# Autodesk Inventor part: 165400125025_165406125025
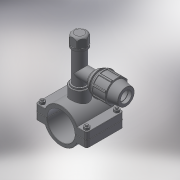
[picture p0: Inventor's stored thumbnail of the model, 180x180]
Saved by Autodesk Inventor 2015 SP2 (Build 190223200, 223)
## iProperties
Created: 2017-05
Part Number: 165400125025_165406125025
Material: Generic
Description: PLASSON TAPPER FOR PE+PVC PIPE 125-25
Document SubType Name: Modeling
Designer: KIM
Density: 1 g/cm^3
Appearance: Default
Author: KIM
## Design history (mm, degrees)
derived "16540.ipt"
feature "Solid1::16540.ipt"
feature "Solid2::16540.ipt"
tag "TaggingFeature1"
body "Solid1"
other parameters: "d0" = 137.5, "d1" = 184, "d2" = 62.5, "d3" = 125, "d4" = 124, "d5" = 0, "d6" = 9.2, "d7" = 184, "d8" = 0.1, "d10" = 0, "d11" = 1.25, "d14" = 39.3783, "d20" = 1.25, "d23" = 1.25, "d36" = 13, "d37" = 10.4, "d38" = 70.5, "d39" = 0, "d40" = 3, "d41" = 5, "d42" = 0, "d43" = 8, "d44" = 3, "d45" = 0, "d46" = 1.25, "d51" = 94, "d52" = 30.291, "d53" = 21, "d54" = 0, "d55" = 25, "d57" = 0, "d58" = 135, "d60" = 0, "d62" = 13, "d63" = 10.4, "d66" = 103.2, "d67" = 25, "d68" = 8.75, "d69" = 21, "d70" = 54, "d71" = 40.5, "d72" = 1.5, "d73" = 43.2, "d74" = 120 deg, "d75" = 37.5, "d76" = 10 deg, "d77" = 48.6, "d78" = 31.5, "d79" = 61, "d81" = 105, "d82" = 6.1, "d87" = 15, "d90" = 50.22, "d91" = 35 deg, "d92" = 17.5 deg, "d94" = 0, "d96" = 360 deg, "d98" = 0.5, "d99" = 67.1, "d100" = 27.2619, "d101" = 135 deg, "d102" = 1.08, "d105" = 2.7, "d106" = 0, "d107" = 0.1, "d108" = 27.2619, "d109" = 33.3201, "d111" = 26.2, "d112" = 6.55, "d113" = 3.5, "d116" = 0, "d118" = 21, "d119" = 0, "d121" = 131, "d122" = 58, "d_" = 125, "B_" = 25, "G_" = 30.291, "A_" = 94, "L_" = 184, "L_1" = 124, "l_2" = 21, "d_1" = 25, "E_" = 54, "l_" = 61, "H_" = 105, "H_1" = 58, "H_2" = 131
